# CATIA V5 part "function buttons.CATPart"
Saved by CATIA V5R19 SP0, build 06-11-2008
Part number: function buttons
Bounding box of the stored display mesh (mm): x 8.082 to 36.456, y -15.893 to 15.893, z 0.762 to 1.012
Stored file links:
  F:\CAD\ipod\function buttons.CATPart
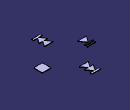
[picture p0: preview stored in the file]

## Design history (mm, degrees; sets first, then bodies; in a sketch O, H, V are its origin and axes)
Body1 (main body)
  DatumSurface1
  DatumCurve1
  DatumCurve2
  Sketch1 on face of DatumSurface1, origin (0, 0, 0.762), H (1, 0, 0), V (0, 1, 0)
    construction line L1 (-3.4224, 0) -> (61.8076, 0)
    point P1 (-3.4224, 0)
    construction line L2 (21.59, 36.0636) -> (21.59, -27.4113)
    reference projected circle E1 centre (21.59, 0) radius 7.62 from edge of DatumCurve1
    reference projected circle E2 centre (21.59, 0) radius 7.62 from edge of DatumCurve2
    point P5 (19.29, 14.8926)
    line L3 (19.29, 14.8926) -> (21.2973, 14.8926)
    line L4 (23.89, 14.8926) -> (23.89, 15.8926)
    line L5 (23.89, 15.8926) -> (19.29, 15.8926)
    line L6 (19.29, 15.8926) -> (19.29, 14.8926)
    point P6 (23.89, 14.8926)
    point P7 (23.89, 15.8926)
    point P8 (19.29, 15.8926)
    point P9 (21.2973, 14.8926)
    line L7 (21.2973, 14.8926) -> (19.29, 12.0171)
    point P10 (19.29, 12.0171)
    line L8 (19.29, 12.0171) -> (21.2064, 12.0171)
    point P11 (21.2064, 12.0171)
    line L9 (21.2064, 12.0171) -> (19.29, 9.2152)
    point P12 (19.29, 9.2152)
    line L10 (19.29, 9.2152) -> (23.89, 9.2152)
    point P13 (23.89, 9.2152)
    line L11 (23.89, 9.2152) -> (21.9736, 12.0171)
    point P14 (21.9736, 12.0171)
    line L12 (21.9736, 12.0171) -> (23.89, 12.0171)
    point P15 (23.89, 12.0171)
    line L13 (23.89, 12.0171) -> (21.8827, 14.8926)
    point P16 (21.8827, 14.8926)
    line L14 (21.8827, 14.8926) -> (23.89, 14.8926)
    point P17 (23.89, -9.2152)
    point P18 (19.29, -9.2152)
    line L15 (19.29, -9.2152) -> (23.89, -9.2152)
    point P19 (21.2064, -12.0171)
    line L16 (21.2064, -12.0171) -> (19.29, -9.2152)
    point P20 (21.9736, -12.0171)
    line L17 (23.89, -9.2152) -> (21.9736, -12.0171)
    point P21 (23.89, -12.0171)
    line L18 (21.9736, -12.0171) -> (23.89, -12.0171)
    point P22 (19.29, -12.0171)
    line L19 (19.29, -12.0171) -> (21.2064, -12.0171)
    point P23 (21.2973, -14.8926)
    line L20 (21.2973, -14.8926) -> (19.29, -12.0171)
    point P24 (21.8827, -14.8926)
    line L21 (23.89, -12.0171) -> (21.8827, -14.8926)
    point P25 (23.89, -14.8926)
    line L22 (21.8827, -14.8926) -> (23.89, -14.8926)
    point P26 (23.89, -15.8926)
    line L23 (23.89, -14.8926) -> (23.89, -15.8926)
    point P27 (19.29, -15.8926)
    line L24 (23.89, -15.8926) -> (19.29, -15.8926)
    point P28 (19.29, -14.8926)
    line L25 (19.29, -15.8926) -> (19.29, -14.8926)
    line L26 (19.29, -14.8926) -> (21.2973, -14.8926)
    point P29 (10.382, 0.3637)
    line L27 (10.382, 0.3637) -> (8.082, -2.8525)
    point P30 (8.082, -2.8525)
    line L28 (8.082, -2.8525) -> (12.682, -2.8525)
    point P31 (12.682, -2.8525)
    line L29 (12.682, -2.8525) -> (10.382, 0.3637)
    axis line L30 (10.382, 11.1664) -> (10.382, -8.6654)
    line L31 (8.082, 0.4956) -> (12.682, 0.4956)
    line L32 (12.682, 0.4956) -> (12.682, 0.9956)
    line L33 (12.682, 0.9956) -> (8.082, 0.9956)
    line L34 (8.082, 0.9956) -> (8.082, 0.4956)
    point P38 (8.082, 1.75)
    line L35 (8.082, 1.75) -> (12.682, 1.75)
    line L36 (12.682, 1.75) -> (12.682, 2.25)
    line L37 (12.682, 2.25) -> (8.082, 2.25)
    line L38 (8.082, 2.25) -> (8.082, 1.75)
    point P40 (12.682, 2.25)
    point P42 (31.9562, 2.25)
    line L39 (31.9562, 2.25) -> (36.4562, 2.25)
    line L40 (36.4562, 2.25) -> (36.4562, -2.25)
    line L41 (36.4562, -2.25) -> (31.9562, -2.25)
    line L42 (31.9562, -2.25) -> (31.9562, 2.25)
    radius E1 = 7.62 (reference)
    distance L2 E2 = 7.62
    length L4 = 1
    length L5 = 4.6
    length L6 = 1
    length L34 = 0.5
    length L28 = 4.6
    length L33 = 4.6
    length L36 = 0.5
    length L39 = 4.5
    length L40 = 4.5
    coincidence: P1 H, P10 L6, P12 L6, P13 L4, P14 L8, P15 L4, P29 L30, P38 L34, P40 L32, P42 L37
    horizontal: L1 H, L3 H, L5 H, L8 H, L10 H, L12 H, L14 H, L28 H, L31 H, L33 H, L35 H, L37 H, L39 H, L41 H
    vertical: L2 V, L4 V, L6 V, L30 V, L32 V, L34 V, L36 V, L38 V, L40 V, L42 V
    symmetry: L6 L4 L2, L9 L11 L2, L7 L13 L2, P13 P17 L1, P12 P18 L1, L10 L15 L1, P11 P19 L1, L9 L16 L1, P14 P20 L1, L11 L17 L1, P15 P21 L1, L12 L18 L1, P10 P22 L1, L8 L19 L1, P9 P23 L1, L7 L20 L1, P16 P24 L1, L13 L21 L1, P6 P25 L1, L14 L22 L1, P7 P26 L1, L4 L23 L1, P8 P27 L1, L5 L24 L1, P5 P28 L1, L6 L25 L1, L3 L26 L1, P30 P31 L30, L34 L32 L30, L39 L41 L1
    fix: L10
  Pad1: profile Sketch1, direction (0, 0, 1), length 0.25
